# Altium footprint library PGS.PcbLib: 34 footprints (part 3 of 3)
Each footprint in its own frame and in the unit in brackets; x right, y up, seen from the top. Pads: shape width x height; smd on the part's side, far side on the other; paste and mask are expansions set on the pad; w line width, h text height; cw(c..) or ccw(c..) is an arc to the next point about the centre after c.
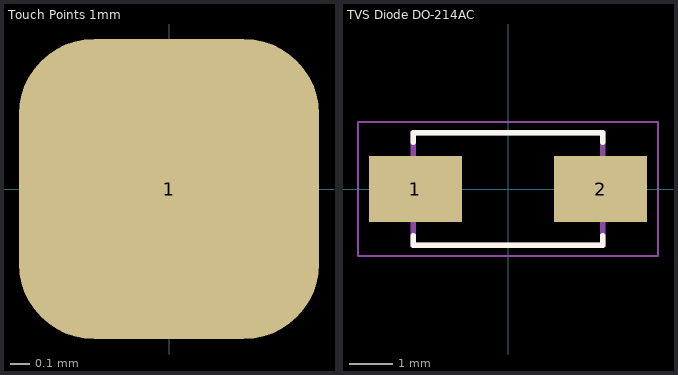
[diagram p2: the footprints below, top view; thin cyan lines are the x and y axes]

## Touch Points 1mm [mil] "Touch Points 0.75mm to1mm"
pads (1):
  rrect50% 60x60 smd: 1(0,0)

## TVS Diode DO-214AC [mm] "TVS Diode BiDirectional LittileFuse SMT 1.5SMC6.8CA DO-214AC 6V8C"
pads (2):
  rect 2.12x1.5 smd: 1(-2.115,0) 2(2.115,0)
Top Overlay:
  lines w0.127: -2.165,-1.07 -2.165,-1.28 2.165,-1.28 2.165,-1.07 ; -2.165,1.07 -2.165,1.28 2.165,1.28 2.165,1.07
Mechanical 13:
  lines w0.127: -2.165,-1.28 2.165,-1.28 2.165,1.28 -2.165,1.28 -2.165,-1.28
Mechanical 15:
  lines w0.05: -3.425,-1.53 3.425,-1.53 3.425,1.53 -3.425,1.53 -3.425,-1.53
3D body "SMAJ12A.STEP": height 2.4, standoff 0, extent -2.605,-1.27 2.605,1.335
